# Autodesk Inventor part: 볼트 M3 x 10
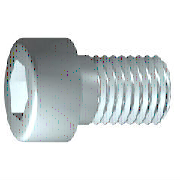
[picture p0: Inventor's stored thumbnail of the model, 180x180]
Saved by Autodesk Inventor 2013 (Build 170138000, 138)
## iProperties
Created: 2012-02
Part Number: 볼트 M3 x 10
Material: 스테인리스강
Description: 6각 소켓 머리 캡 나사
Document SubType Name: Modeling
Standard: ISO 4762
Designer: mduedu
Standard Revision: Fourth edition 2004-03-01
Standards Organization: ISO
Language: ko-KR
Size Designation: M3 x 10
Categories: <MemberInstance><Categories><Category DisplayName="조임쇠" InternalName="e4da775c-781d-43d5-af7c-5136215cf5a6" Mnemonic="FSTN"><Category DisplayName="볼트" InternalN
Density: 8.08 g/cm^3
Mass: 1.0701 g
Surface Area: 2.01851 cm^2
Volume: 0.132438 cm^3
IsCustomPart: 0
Author: mduedu
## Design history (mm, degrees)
sketch "스케치1"
  geometry: L1 (-0.867, 0)-(10, 0); L2 (10, 0)-(10, 1.5); L3 (10, 1.5)-(1.25, 1.5); L4 (1.25, 1.5)-(0.943, 1.5); L5 (0.943, 1.5)-(0, 1.5); L6 (0, 1.5)-(0, 2.75); L7 (0, 2.75)-(-3, 2.75); L8 (-3, 2.75)-(-3, 1.443); L9 (-3, 1.443)-(-1.7, 1.443); L10 (-1.7, 1.443)-(-0.867, 0); L11 (-5.6, 0)-(12.6, 0) reference; L12 (0, -0.55)-(0, 3.3) reference; L13 (1.25, 1.5)-(0, 1.5)
  constraints: 22 end point, 6 parallel, 2 collinear, 2 perpendicular, 1 horizontal, 1 point on line
  dimensions: "d1" = 8.75 distance from line of L3.end L2 (= GEL); "d2" = 0.30683 distance of L4.end L3.end (computed from GAL); "d3" = 3 distance between parallel lines of L8 L6 (= KOH); "d4" = 1.3 distance of L8.end L9.end (= INTI); "d5" = 60 deg angle of L10 L1; "d6" = 3 diameter of L3 L1 (= GD); "d7" = 3 diameter of L5 L1 (= BDM); "d8" = 2.88675 diameter of L9 L1 (= 1.1547 x SW); "d9" = 5.5 diameter of L7 L1 (= KOD); "d26" = 10 distance between parallel lines of L12 L2 (= NLG)
revolve "본체" sketch "스케치1" stored, may be unused: angle "d10" = 90 deg
sketch "스케치2"
  geometry: L1 (0, -3.85)-(0, 3.85) reference; L2 (-3.85, 0)-(3.85, 0) reference; L3 (1.443, 0)-(0.722, -1.25); L4 (0.722, -1.25)-(-0.722, -1.25); L5 (-0.722, -1.25)-(-1.443, 0); L6 (-1.443, 0)-(-0.722, 1.25); L7 (-0.722, 1.25)-(0.722, 1.25); L8 (0.722, 1.25)-(1.443, 0); 2 further points
  constraints: 12 end point, 1 coincident, 1 horizontal alignment, 1 point on line, 12 other
extrude "슬롯" join sketch "스케치2" stored distance "d11" = 10; taper "d12" = 0 deg
workplane "Work Plane1"
fillet "Fillet2" dims "d30" = 0.1 (= R)
body "Solid1"
fillet "모깎기1" dims "d17" = 0.3 (= RR)
feature "스레드" dims "d13" = 8.75 (= GEL), "d14" = 0
chamfer "모따기1" distance "d15" = 0.30673 (= -0.5 x SPD + 0.5 x GD); stored, may be unused: second distance "d16" = 0.30673 (= GUL), angle "d27" = 45 deg
other parameters: "GD" = 3 [user parameter; used in 2 equation terms], "NLG" = 10 [user parameter; used in 1 equation term], "GEL" = 8.75 [user parameter; used in 2 equation terms], "KOD" = 5.5 [user parameter; used in 1 equation term], "KOH" = 3 [user parameter; used in 1 equation term], "INTI" = 1.3 [user parameter; used in 1 equation term], "GAL" = 0.30673 (= 0.61345 x PTC) [user parameter; used in 1 equation term], "GUL" = 0.30673 (= 0.61345 x PTC) [user parameter; used in 1 equation term], "BDM" = 3 (= NND) [user parameter; used in 1 equation term], "SW" = 2.5 [user parameter; used in 2 equation terms], "RR" = 0.3 [user parameter; used in 1 equation term], "SPD" = 2.38655 (= NND - 1.2269 x PTC) [user parameter; used in 1 equation term], "d19" = 0, "d28" = 0, "d29" = 0, "R" = 0.1 [user parameter; used in 1 equation term], "TOA" = 30 deg [user parameter], "GD1" = 2.38655 (= THREADDIA - 1.2269 x PTC) [user parameter], "THREADDIA" = 3 [user parameter; used in 1 equation term], "FAWI" = 45 deg [user parameter], "PTC" = 0.5 [user parameter; used in 5 equation terms], "NND" = 3 [user parameter; used in 2 equation terms], "E0" = 2.8875 (= 1.155 x SW) [user parameter]
